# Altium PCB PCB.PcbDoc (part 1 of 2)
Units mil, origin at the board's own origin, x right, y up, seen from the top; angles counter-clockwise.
Board outline 2952.76 x 1850.39 mil, 2 copper layers (Top Layer, Bottom Layer), stack 21 mil thick; 67 components, 133 nets, 435 pads, 333 vias.
Unrouted connection lines stored in the file: 207.
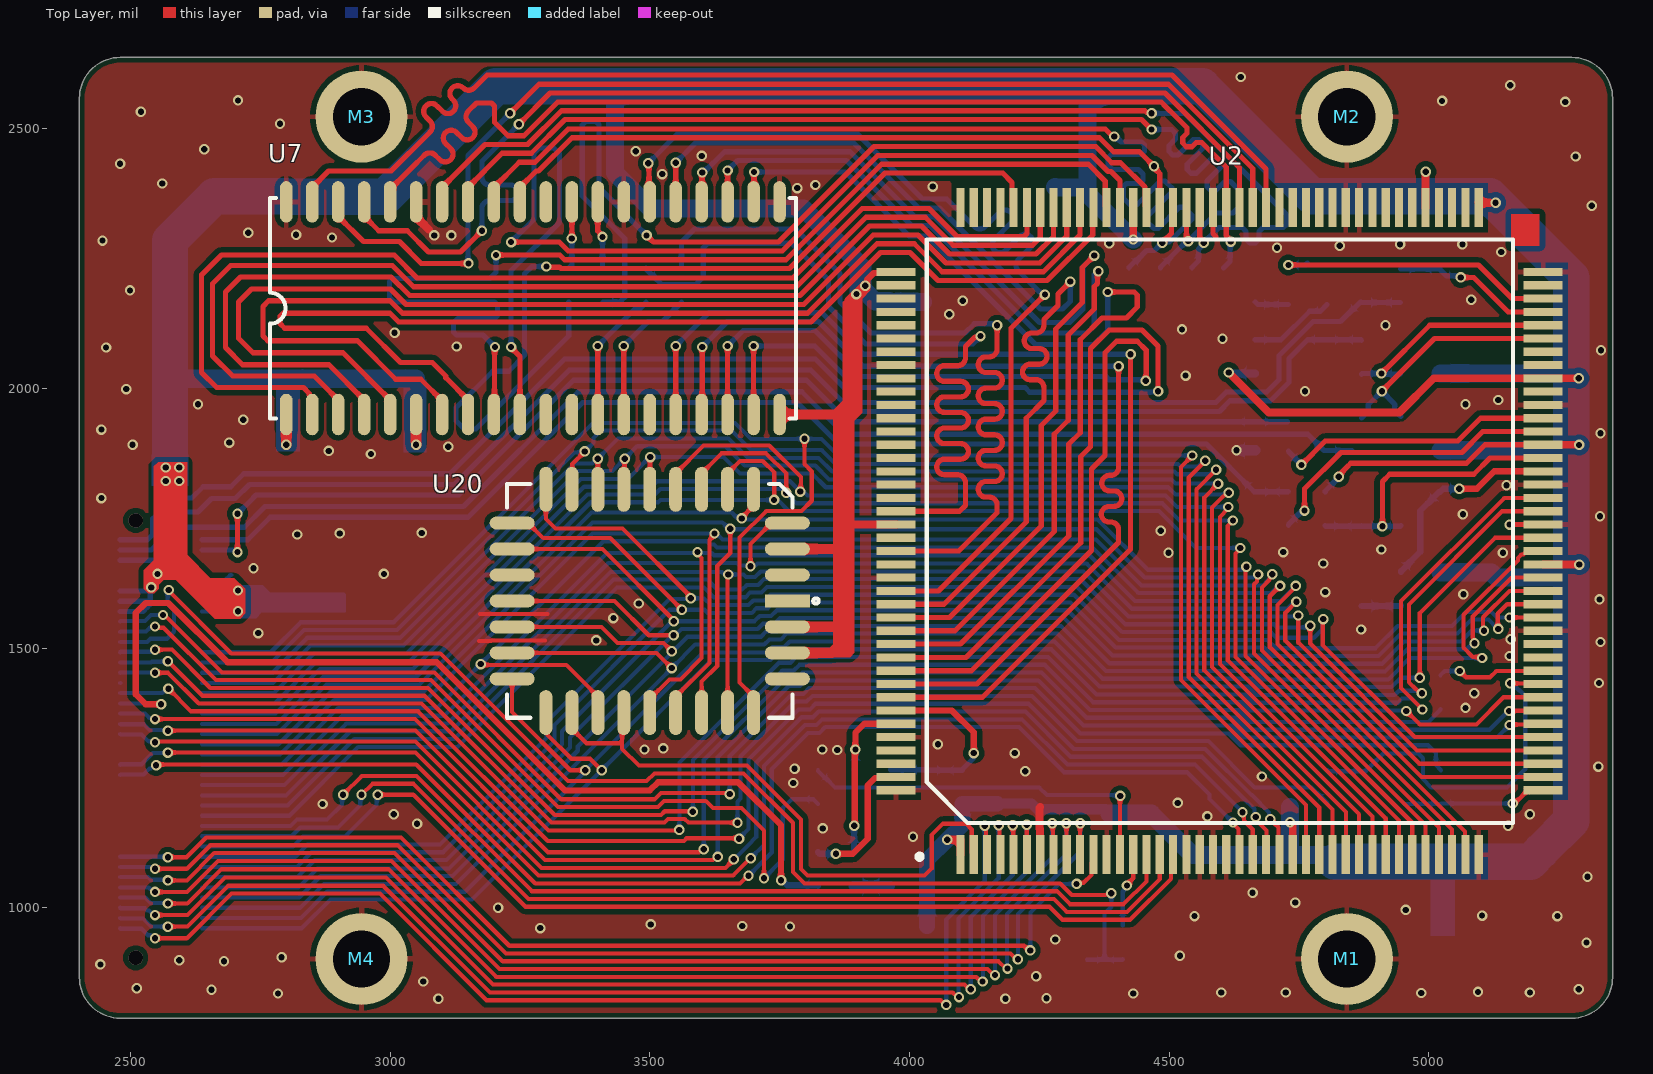
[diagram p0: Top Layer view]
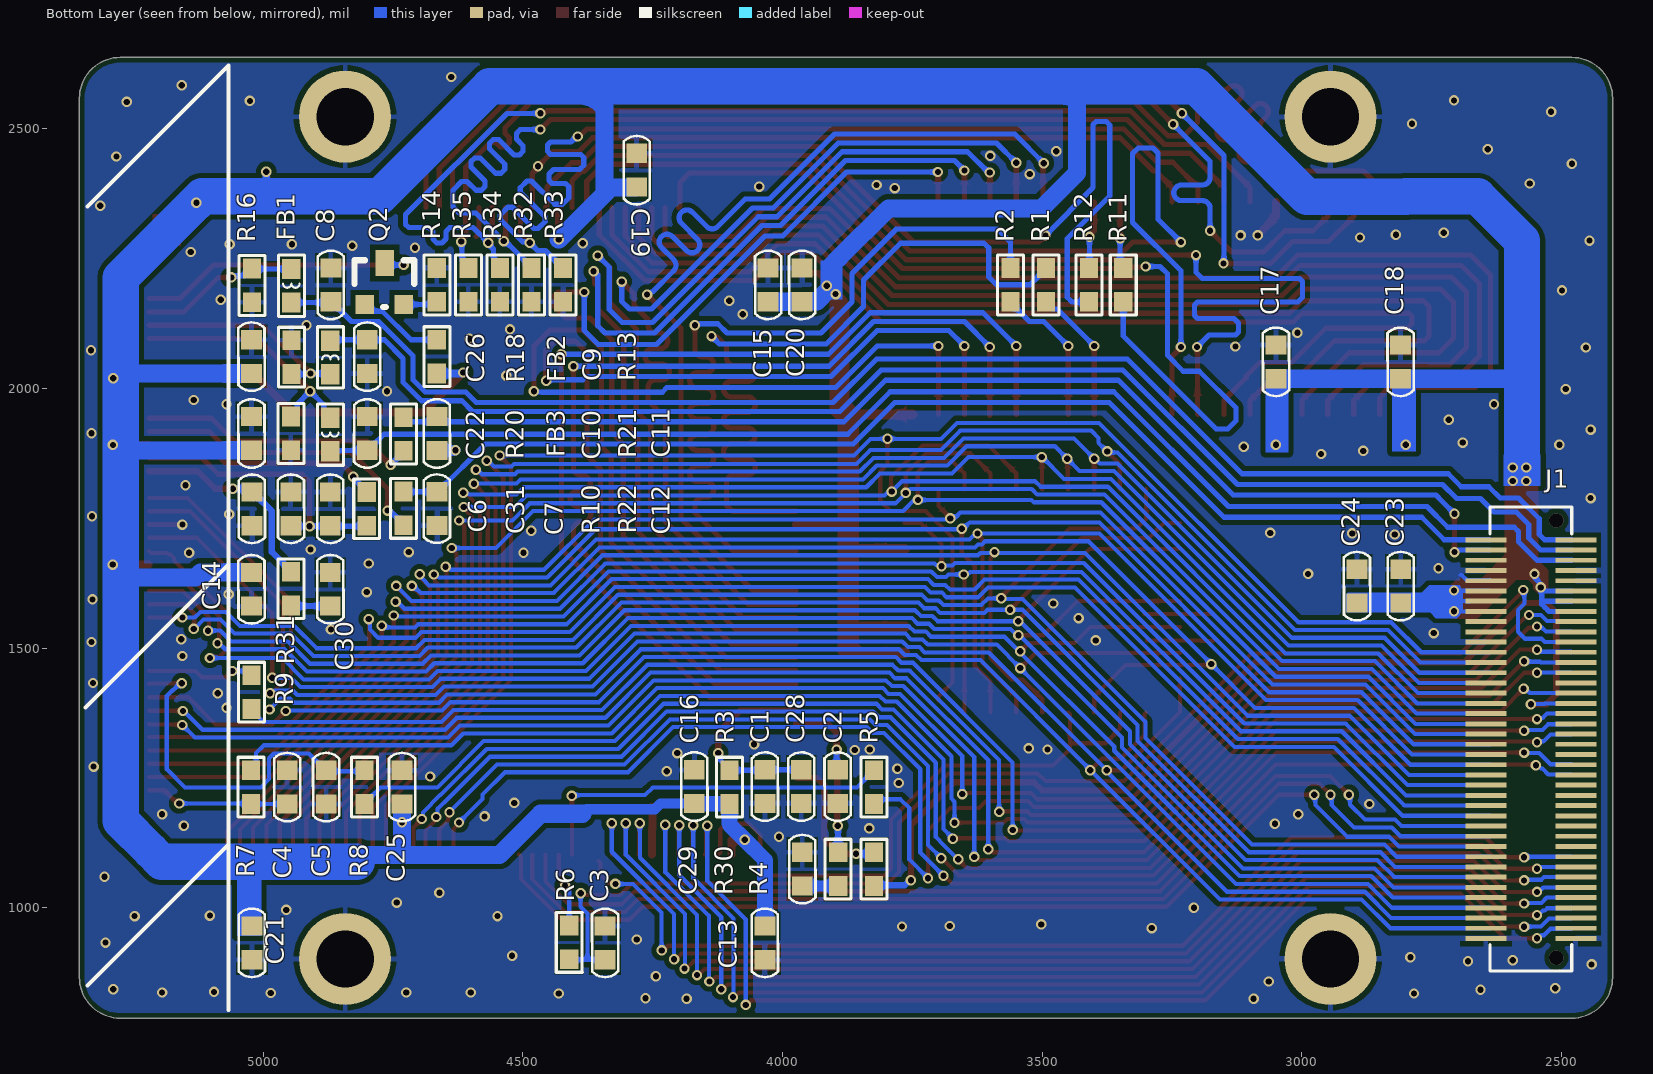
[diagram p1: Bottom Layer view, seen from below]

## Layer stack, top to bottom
Top Solder: solder mask 0.4, Solder Resist, Dk 3.5
Top Layer: signal copper 1.4
Dielectric 1: prepreg 2.8, Composite dielectric, Dk 4.1
Dielectric1: prepreg 12.6, Composite dielectric, Dk 4.1
Dielectric 2: prepreg 2.8, Composite dielectric, Dk 4.1
Bottom Layer: signal copper 1.4
Bottom Solder: solder mask 0.4, Solder Resist, Dk 3.5

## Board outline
2401.57,866.14 ccw(c2480.31,866.14) 2480.31,787.4 5275.59,787.4 ccw(c5275.59,866.14) 5354.33,866.14 5354.33,2559.06 ccw(c5275.59,2559.06) 5275.59,2637.8 2480.31,2637.8 ccw(c2480.31,2559.06) 2401.57,2559.06

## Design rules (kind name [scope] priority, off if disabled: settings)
BoardOutlineClearance [All] p1: gap=0 ignorepadtopadclearanceinfootprint=FALSE except(10: Poly-OutlineEdge Poly-CavityEdge Poly-CutoutEdge Poly-SplitBarrior)
Clearance [All] p1: gap=7 ignorepadtopadclearanceinfootprint=FALSE except(0: Arc-Hole Track-Hole SMDPad-Hole THPad-Hole Via-Hole Fill-Hole Poly-Hole Region-Hole Text-Hole; 10: Arc-Fill Arc-Poly Arc-Region Track-Fill Track-Poly Track-Region SMDPad-Fill SMDPad-Poly SMDPad-Region THPad-Fill THPad-Poly THPad-Region Via-Fill Via-Poly Via-Region Fill-Fill Fill-Poly Fill-Region Poly-Poly Poly-Region Region-Region)
ComponentClearance [All] p1: gap=0 collisioncheckmode=3 verticalgap=0 showdistances=FALSE
HoleSize [All] p1: absolutevalues=TRUE maxlimit=1000 minlimit=1 maxpercent=80.000 minpercent=20.000
HoleToHoleClearance [All] p1: gap=0 allowstackedmicrovias=TRUE
MinimumSolderMaskSliver [All] p1: minsoldermaskwidth=0
PlaneClearance [All] p1: clearance=0
PolygonConnect PolygonConnect_1 [InNet('GND')] p1: thpad.connectstyle=Relief thpad.reliefconductorwidth=10 thpad.reliefentries=4 thpad.polygonreliefangle="90 Angle" thpad.airgapwidth=10 smdpad.connectstyle=Relief smdpad.reliefconductorwidth=10 smdpad.reliefentries=4 smdpad.polygonreliefangle="90 Angle" smdpad.airgapwidth=10 via.connectstyle=Direct via.reliefconductorwidth=10 via.reliefentries=4 via.polygonreliefangle="90 Angle" via.airgapwidth=10
PolygonConnect [All] p2: connectstyle=Direct reliefconductorwidth=10 reliefentries=4 polygonreliefangle="90 Angle" airgapwidth=10
RoutingVias [All] p1: holewidth=14 width=27 viastyle="Through Hole" minholewidth=10 minwidth=18 maxholewidth=50 maxwidth=100
SilkToSilkClearance [All] p1: silktosilkclearance=0
SilkToSolderMaskClearance [IsPad] p1: minsilkscreentomaskgap=0 clearancetoexposedcopper=TRUE
SolderMaskExpansion [All] p1: expansion=4 istentingtop=FALSE
Width [All] p1: maxlimit=200 minlimit=8 preferedwidth=8 minimp=50.000000 maximp=50.000000 favimp=50.000000
23 further rules are at their usual default settings.

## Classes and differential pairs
net class RAM-D: MD16 MD17 MD18 MD19 MD20 MD21 MD22 MD23 MD24 MD25 MD26 MD27 MD28 MD29 MD30 MD31
net class RAM-A: CAS# NetR1_2 NetR2_2 NetR11_1 NetR12_1 RAS# VA0 VA1 VA2 VA3 VA4 VA5 VA6 VA7 VA8 WE2# WE3#

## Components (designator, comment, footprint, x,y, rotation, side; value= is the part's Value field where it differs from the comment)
C1 "0.1uf" C0603 4034,1266 r270 bottom
C2 "0.1uf" C0603 3894,1266 r270 bottom
C3 "47pf" C0603 4342,900 r90 bottom
C4 "470pf" C0603 4954,1200 r90 bottom
C5 "47pf" C0603 4879,1264.96 r270 bottom
C6 "0.1uf" C0603 5022,1800.96 r270 bottom
C7 "0.1uf" C0603 4871,1736 r90 bottom
C8 "47pf" C0603 4870,2167 r90 bottom
C9 "47pf" C0603 4800,2093.98 r270 bottom
C10 "47pf" C0603 4800,1881 r90 bottom
C11 "47pf" C0603 4665.75,1945.96 r270 bottom
C12 "47pf" C0603 4665.75,1801.23 r270 bottom
C13 "10uf" C0603 4034,964.96 r270 bottom
C14 "0.1uf" C0603 5022.75,1646 r270 bottom
C15 "0.1uf" C0603 4028,2167.04 r90 bottom
C16 "0.1uf" C0603 4170,1201.04 r90 bottom
C17 "0.1uf" C0603 3050,2019.02 r90 bottom
C18 "0.1uf" C0603 2810,2019.02 r90 bottom
C19 "0.1uf" C0603 4281,2388 r90 bottom
C20 "10uf" C0603 3962.65,2167.04 r90 bottom
C21 "10uf" C0603 5022,964.96 r270 bottom
C22 "0.1uf" C0603 5023,1881 r90 bottom
C23 "10uf" C0603 2809.75,1587.04 r90 bottom
C24 "10uf" C0603 2894,1587.04 r90 bottom
C25 "0.1uf" C0603 4733,1200 r90 bottom
C26 "0.1uf" C0603 5023,2029 r90 bottom
C28 "10uf" C0603 3964,1266 r270 bottom
C29 "1uf" C0603 3962,1042 r90 bottom
C30 "1uf" C0603 4871,1581.04 r90 bottom
C31 "0.1uf" C0603 4947,1736 r90 bottom
FB1 "68R 100Mhz" L0603 4946,2198 r90 bottom
FB2 "68R 100Mhz" L0603 4871,2060 r270 bottom
FB3 "68R 100Mhz" L0603 4871,1911.28 r90 bottom
J1 "CON40x2" BTB0.5-80P 2480.31,940.94 r90 bottom locked
M1 "CON1" M2.5 4842.52,901.57 r0 top locked
M2 "CON1" M2.5 4842.52,2523.62 r0 top locked
M3 "CON1" M2.5 2944.88,2523.62 r0 top locked
M4 "CON1" M2.5 2944.88,901.57 r0 top locked
Q2 "3904" SOT23 4767,2202 r180 bottom
R1 "33" R0603 3493,2167 r90 bottom
R2 "33" R0603 3561,2167 r90 bottom
R3 "33" R0603 4102,1200 r90 bottom
R4 "33" R0603 3824,1042 r90 bottom
R5 "33" R0603 3824,1200 r90 bottom
R6 "33" R0603 4411,901 r90 bottom
R7 "1k" R0603 5024,1265 r270 bottom
R8 "33" R0603 4805,1265 r270 bottom
R9 "33" R0603 5023.1,1448 r270 bottom
R10 "33" R0603 4801,1736 r90 bottom
R11 "33" R0603 3344,2167 r90 bottom
R12 "33" R0603 3410,2167 r90 bottom
R13 "1k" R0603 4666,2093.97 r270 bottom
R14 "360" R0603 4666,2232 r270 bottom
R16 "150" R0603 5022,2166 r90 bottom
R18 "150" R0603 4946,2093 r270 bottom
R20 "150" R0603 4947,1881 r90 bottom
R21 "33" R0603 4729.9,1880 r90 bottom
R22 "33" R0603 4729.9,1736.75 r90 bottom
R30 "75" R0603 3893,1107 r270 bottom
R31 "75" R0603 4947,1647 r270 bottom
R32 "4.7k" R0603 4483.75,2167 r90 bottom
R33 "4.7k" R0603 4423,2167 r90 bottom
R34 "4.7k" R0603 4544.5,2167 r90 bottom
R35 "4.7k" R0603 4605.25,2167 r90 bottom
U2 "GD5422" QFP160 4098.43,1102.36 r90 top locked
U7 "16256" SOJ-40 2800,1950 r90 top locked
U20 "29C512_PLCC32" PLCC32S 3765,1591 r270 top

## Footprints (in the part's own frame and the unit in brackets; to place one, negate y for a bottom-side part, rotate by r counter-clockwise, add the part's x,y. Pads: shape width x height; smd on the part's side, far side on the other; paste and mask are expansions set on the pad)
BTB0.5-80P [mm]
  rect 0.24x2 smd: 1(0,-0.2) 2(0,4.2) 3(0.5,-0.2) 4(0.5,4.2) 5(1,-0.2) 6(1,4.2) 7(1.5,-0.2) 8(1.5,4.2) 9(2,-0.2) 10(2,4.2) 11(2.5,-0.2) 12(2.5,4.2) 13(3,-0.2) 14(3,4.2) 15(3.5,-0.2) 16(3.5,4.2) 17(4,-0.2) 18(4,4.2) 19(4.5,-0.2) 20(4.5,4.2) 21(5,-0.2) 22(5,4.2) 23(5.5,-0.2) 24(5.5,4.2) 25(6,-0.2) 26(6,4.2) 27(6.5,-0.2) 28(6.5,4.2) 29(7,-0.2) 30(7,4.2) 31(7.5,-0.2) 32(7.5,4.2) 33(8,-0.2) 34(8,4.2) 35(8.5,-0.2) 36(8.5,4.2) 37(9,-0.2) 38(9,4.2) 39(9.5,-0.2) 40(9.5,4.2) 41(10,-0.2) 42(10,4.2) 43(10.5,-0.2) 44(10.5,4.2) 45(11,-0.2) 46(11,4.2) 47(11.5,-0.2) 48(11.5,4.2) 49(12,-0.2) 50(12,4.2) 51(12.5,-0.2) 52(12.5,4.2) 53(13,-0.2) 54(13,4.2) 55(13.5,-0.2) 56(13.5,4.2) 57(14,-0.2) 58(14,4.2) 59(14.5,-0.2) 60(14.5,4.2) 61(15,-0.2) 62(15,4.2) 63(15.5,-0.2) 64(15.5,4.2) 65(16,-0.2) 66(16,4.2) 67(16.5,-0.2) 68(16.5,4.2) 69(17,-0.2) 70(17,4.2) 71(17.5,-0.2) 72(17.5,4.2) 73(18,-0.2) 74(18,4.2) 75(18.5,-0.2) 76(18.5,4.2) 77(19,-0.2) 78(19,4.2) 79(19.5,-0.2) 80(19.5,4.2)
  silkscreen extent -1.6,0 21.1,4
C0603 [mil]
  rect 37.01x40 smd: 1(0,0)
  rect 37x40 smd: 2(64.98,0)
  silkscreen extent -34,-25 98,25
L0603 [mm]
  rect 1x0.9 smd: 1(-0.82,0) 2(0.82,0)
  silkscreen extent -1.5,-0.64 1.5,0.64
M2.5 [mm]
  round 4.5 hole 2.8: 1(0,0)
PLCC32S [mil]
  rect 25x86.61 smd: 1(0,0)
  oval 25x86.61 smd: 2(-50,0) 3(-100,0) 4(-150,0) 14(-150,-530) 15(-100,-530) 16(-50,-530) 17(0,-530) 18(50,-530) 19(100,-530) 20(150,-530) 30(150,0) 31(100,0) 32(50,0)
  oval 86.61x25 smd: 5(-215,-65) 6(-215,-115) 7(-215,-165) 8(-215,-215) 9(-215,-265) 10(-215,-315) 11(-215,-365) 12(-215,-415) 13(-215,-465) 21(215,-465) 22(215,-415) 23(215,-365) 24(215,-315) 25(215,-265) 26(215,-215) 27(215,-165) 28(215,-115) 29(215,-65)
  silkscreen extent -225,-540 225,60
QFP160 [mm] "160-Pin Plastic Quad Flat Pack (PQFP)"
  rect 1.9x0.4 smd: 1(0,0) 2(0,-0.65) 3(0,-1.3) 4(0,-1.95) 5(0,-2.6) 6(0,-3.25) 7(0,-3.9) 8(0,-4.55) 9(0,-5.2) 10(0,-5.85) 11(0,-6.5) 12(0,-7.15) 13(0,-7.8) 14(0,-8.45) 15(0,-9.1) 16(0,-9.75) 17(0,-10.4) 18(0,-11.05) 19(0,-11.7) 20(0,-12.35) 21(0,-13) 22(0,-13.65) 23(0,-14.3) 24(0,-14.95) 25(0,-15.6) 26(0,-16.25) 27(0,-16.9) 28(0,-17.55) 29(0,-18.2) 30(0,-18.85) 31(0,-19.5) 32(0,-20.15) 33(0,-20.8) 34(0,-21.45) 35(0,-22.1) 36(0,-22.75) 37(0,-23.4) 38(0,-24.05) 39(0,-24.7) 40(0,-25.35) 81(31.65,-25.35) 82(31.65,-24.7) 83(31.65,-24.05) 84(31.65,-23.4) 85(31.65,-22.75) 86(31.65,-22.1) 87(31.65,-21.45) 88(31.65,-20.8) 89(31.65,-20.15) 90(31.65,-19.5) 91(31.65,-18.85) 92(31.65,-18.2) 93(31.65,-17.55) 94(31.65,-16.9) 95(31.65,-16.25) 96(31.65,-15.6) 97(31.65,-14.95) 98(31.65,-14.3) 99(31.65,-13.65) 100(31.65,-13) 101(31.65,-12.35) 102(31.65,-11.7) 103(31.65,-11.05) 104(31.65,-10.4) 105(31.65,-9.75) 106(31.65,-9.1) 107(31.65,-8.45) 108(31.65,-7.8) 109(31.65,-7.15) 110(31.65,-6.5) 111(31.65,-5.85) 112(31.65,-5.2) 113(31.65,-4.55) 114(31.65,-3.9) 115(31.65,-3.25) 116(31.65,-2.6) 117(31.65,-1.95) 118(31.65,-1.3) 119(31.65,-0.65) 120(31.65,0)
  rect 0.4x1.9 smd: 41(3.15,-28.5) 42(3.8,-28.5) 43(4.45,-28.5) 44(5.1,-28.5) 45(5.75,-28.5) 46(6.4,-28.5) 47(7.05,-28.5) 48(7.7,-28.5) 49(8.35,-28.5) 50(9,-28.5) 51(9.65,-28.5) 52(10.3,-28.5) 53(10.95,-28.5) 54(11.6,-28.5) 55(12.25,-28.5) 56(12.9,-28.5) 57(13.55,-28.5) 58(14.2,-28.5) 59(14.85,-28.5) 60(15.5,-28.5) 61(16.15,-28.5) 62(16.8,-28.5) 63(17.45,-28.5) 64(18.1,-28.5) 65(18.75,-28.5) 66(19.4,-28.5) 67(20.05,-28.5) 68(20.7,-28.5) 69(21.35,-28.5) 70(22,-28.5) 71(22.65,-28.5) 72(23.3,-28.5) 73(23.95,-28.5) 74(24.6,-28.5) 75(25.25,-28.5) 76(25.9,-28.5) 77(26.55,-28.5) 78(27.2,-28.5) 79(27.85,-28.5) 80(28.5,-28.5) 121(28.5,3.15) 122(27.85,3.15) 123(27.2,3.15) 124(26.55,3.15) 125(25.9,3.15) 126(25.25,3.15) 127(24.6,3.15) 128(23.95,3.15) 129(23.3,3.15) 130(22.65,3.15) 131(22,3.15) 132(21.35,3.15) 133(20.7,3.15) 134(20.05,3.15) 135(19.4,3.15) 136(18.75,3.15) 137(18.1,3.15) 138(17.45,3.15) 139(16.8,3.15) 140(16.15,3.15) 141(15.5,3.15) 142(14.85,3.15) 143(14.2,3.15) 144(13.55,3.15) 145(12.9,3.15) 146(12.25,3.15) 147(11.6,3.15) 148(10.95,3.15) 149(10.3,3.15) 150(9.65,3.15) 151(9,3.15) 152(8.35,3.15) 153(7.7,3.15) 154(7.05,3.15) 155(6.4,3.15) 156(5.75,3.15) 157(5.1,3.15) 158(4.45,3.15) 159(3.8,3.15) 160(3.15,3.15)
  silkscreen extent -0.22,-27.03 30.1,2.12
R0603 [mil]
  rect 38x35 smd: 1(0,0) 2(65,0)
  silkscreen extent -25,-25 90,25
SOJ-40 [mil] "薄贴片"
  oval 80x24 smd: 1(0,0) 2(0,-50) 3(0,-100) 4(0,-150) 5(0,-200) 6(0,-250) 7(0,-300) 8(0,-350) 9(0,-400) 10(0,-450) 11(0,-500) 12(0,-550) 13(0,-600) 14(0,-650) 15(0,-700) 16(0,-750) 17(0,-800) 18(0,-850) 19(0,-900) 20(0,-950) 21(409.45,-950) 22(409.45,-900) 23(409.45,-850) 24(409.45,-800) 25(409.45,-750) 26(409.45,-700) 27(409.45,-650) 28(409.45,-600) 29(409.45,-550) 30(409.45,-500) 31(409.45,-450) 32(409.45,-400) 33(409.45,-350) 34(409.45,-300) 35(409.45,-250) 36(409.45,-200) 37(409.45,-150) 38(409.45,-100) 39(409.45,-50) 40(409.45,0)
  silkscreen extent -8,-981 417,31
SOT23 [mil]
  rect 36x36 smd: B(-37.5,-40) E(37.5,-40)
  rect 36x50 smd: C(0.5,40)
  silkscreen extent -58,-45 58,45

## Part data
C1 C2 C13 C14 C15 C16 C17 C18 C19 C20 C21 C22 C23 C24 C25 C26 C28 C29 C30: library part 0CAP
C3 C4 C5 C6 C7 C8 C9 C10 C11 C12 C31: library part CAP
FB1 FB2 FB3: library part L
Q2: library part 0NPN
R1 R2 R3 R4 R5 R6 R7 R8 R9 R10 R11 R12 R13 R14 R16 R18 R20 R21 R22 R30 R31 R32 R33 R34 R35: library part RES2

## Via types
v1: diameter 20, hole 12, Top Layer to Bottom Layer, tented both sides, 331 vias
v2: diameter 27.56, hole 27.56, Top Layer to Bottom Layer, 2 vias

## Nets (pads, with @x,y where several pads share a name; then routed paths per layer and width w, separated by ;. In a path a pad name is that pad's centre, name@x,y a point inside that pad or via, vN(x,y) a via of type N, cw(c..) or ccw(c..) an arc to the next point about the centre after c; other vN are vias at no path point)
A0: J1.58 U2.27 U20.29 | length 3612.3
  Top Layer w8: U20.29@3700,1399 3700,1406.81 3673,1433.81 3673,1713.04 3724.46,1764.5 3792.5,1764.5 3812,1784 3812,1840.38 3798,1854.38 v1(3798,1903.19) ; v1(4544.92,1871) 4544.92,1870.92 4523,1849 4523,1438.59 4763.78,1197.81 U2.27@4763.78,1102.36
  Bottom Layer w8: J1.58@2637.8,1492.13 2770.13,1492.13 2828,1550 3006.87,1550 3390.87,1934 3664,1934 3694.81,1903.19 v1(3798,1903.19) 3830.66,1903.19 3862.85,1871 v1(4544.92,1871)
A1: J1.56 U2.28 U20.12 | length 3115.1
  Top Layer w8: U20.12@3350,1806 3350.73,1806.73 3350.73,1854.73 v1(3375,1879) ; v1(4570,1861) 4538,1829 4538,1444.8 4789.37,1193.43 U2.28@4789.37,1102.36
  Bottom Layer w8: J1.56@2637.8,1472.44 2771.65,1472.44 2834.21,1535 3013.08,1535 3354.79,1876.7 3372.7,1876.7 3391.5,1895.5 3391.5,1904.8 3405.7,1919 3657.79,1919 3695.29,1881.5 3831.14,1881.5 3857.64,1855 4517,1855 4522,1850 4555.75,1850 4566.75,1861 v1(4570,1861)
A2: J1.54 U2.29 U20.11 | length 3096.3
  Top Layer w8: U20.11@3400,1806 v1(3400,1865) ; v1(4590.65,1843.61) 4553,1805.96 4553,1451.02 4814.96,1189.06 U2.29@4814.96,1102.36
  Bottom Layer w8: J1.54@2637.8,1452.76 2773.18,1452.76 2840.43,1520 3019.29,1520 3355.29,1856 3389.31,1856 3398.31,1865 v1(3400,1865) 3439,1904 3651.57,1904 3689.07,1866.5 3824.93,1866.5 3851.43,1840 4510.79,1840 4515.79,1835 4578.8,1835 4587.41,1843.61 v1(4590.65,1843.61)
A3: J1.52 U2.30 U20.10 | length 3072
  Top Layer w8: U20.10@3450,1806 3451,1807 3451,1864 v1(3452,1865) ; v1(4594.61,1816.9) 4568,1790.29 4568,1457.23 4840.55,1184.68 U2.30@4840.55,1102.36
  Bottom Layer w8: J1.52@2637.8,1433.07 2774.71,1433.07 2846.64,1505 3025.51,1505 3361.51,1841 3428,1841 v1(3452,1865) ; v1@3454,1866 3454,1867 3476,1889 3645.36,1889 3682.86,1851.5 3818.71,1851.5 3845.21,1825 4504.57,1825 4512.67,1816.9 v1(4594.61,1816.9)
A4: J1.50 U2.31 U20.9 | length 3088.9
  Top Layer w8: U20.9@3500,1806 3500.5,1806.5 3500.5,1867.5 v1(3501,1868) ; v1(4615.11,1799.33) 4611.86,1799.33 4605.53,1793 4605.3,1793 4583,1770.7 4583,1463.44 4866.14,1180.3 U2.31@4866.14,1102.36
  Bottom Layer w8: J1.50@2637.8,1413.39 2776.24,1413.39 2852.85,1490 3031.72,1490 3367.72,1826 3458,1826 3500,1868 v1(3501,1868) 3642,1868 3673.5,1836.5 3812.5,1836.5 3839,1810 4498.36,1810 4512.46,1795.9 4603.31,1795.9 4604.44,1797.04 4612.82,1797.04 v1(4615.11,1799.33)
A5: J1.48 U2.32 U20.8 | length 3325.4
  Top Layer w8: U20.8@3550,1806 3550,1836.81 3603.5,1890.31 3730.12,1890.31 3791,1829.43 3791,1802.72 v1(3789.78,1801.5) ; v1(4614,1772) 4614,1768.89 4598,1752.89 4598,1469.65 4891.73,1175.92 U2.32@4891.73,1102.36
  Bottom Layer w8: J1.48@2637.8,1393.7 2777.77,1393.7 2859.07,1475 3037.93,1475 3373.93,1811 3503.51,1811 3514.01,1821.5 3770.09,1821.5 3786.01,1805.58 3789.58,1805.58 3791,1807 3804,1794 4493.15,1794 4515.15,1772 v1(4614,1772) ; v1(3789.78,1801.5) v1@3793.14,1804.86
A6: J1.46 U2.33 U20.7 | length 3226.4
  Top Layer w8: U20.7@3600,1806 3600,1836.81 3638.5,1875.31 3723.91,1875.31 3763,1836.21 3763,1799.11 v1(3762.89,1799) ; v1(4623,1746) 4623,1745.31 4613,1735.31 4613,1476.87 4917.32,1172.55 U2.33@4917.32,1102.36
  Bottom Layer w8: J1.46@2637.8,1374.02 2779.3,1374.02 2865.28,1460 3044.15,1460 3380.15,1796 3509.73,1796 3520.23,1806.5 3754.25,1806.5 3761.75,1799 3762.58,1799 3782.58,1779 4486.93,1779 4519.93,1746 v1(4623,1746)
A7: J1.44 U2.34 U20.6 | length 3130.9
  Top Layer w8: U20.6@3650,1806 3650,1836.81 3673.5,1860.31 3717.69,1860.31 3739.92,1838.08 3739.92,1785.91 v1(3739.51,1785.5) ; v1(4637,1693) 4637,1691.31 4628,1682.31 4628,1483.08 4942.91,1168.17 U2.34@4942.91,1102.36
  Bottom Layer w8: J1.44@2637.8,1354.33 2780.82,1354.33 2871.49,1445 3050.36,1445 3386.36,1781 3515.94,1781 3520.44,1785.5 v1@3739.92,1785.5 ; v1@3743,1787 3744.69,1787 3767.69,1764 4480.72,1764 4551.72,1693 v1(4637,1693)
A8: J1.42 U2.35 U20.5 | length 2990
  Top Layer w8: v1(3677,1750) 3677,1751.1 3700,1774.1 U20.5@3700,1806 ; v1(4649,1657) 4647,1655 4647,1485.29 4968.5,1163.79 U2.35@4968.5,1102.36
  Bottom Layer w8: J1.42@2637.8,1334.65 2782.35,1334.65 2877.71,1430 3056.57,1430 3387.57,1761 3658,1761 3669,1750 v1(3677,1750) 3679,1748 4362.54,1748 4459.54,1651 4639.75,1651 4645.75,1657 v1(4649,1657)
A9: J1.40 U2.36 U20.27 | length 3313.4
  Top Layer w8: U20.27@3600,1376 3600,1435.59 3630,1465.59 3630,1658.56 3655,1683.56 v1(3655,1730) ; v1(4671.64,1642) 4669.34,1639.7 4669.34,1628.56 4664,1623.21 4664,1489.51 4994.09,1159.41 U2.36@4994.09,1102.36
  Bottom Layer w8: J1.40@2637.8,1314.96 2784.71,1314.96 2884.75,1415 3062.79,1415 3389.79,1742 3639.75,1742 3651.75,1730 v1(3655,1730) 3656,1729 4360.33,1729 4453.33,1636 4662.39,1636 4668.39,1642 v1(4671.64,1642)
A10: J1.38 U2.37 U20.26 | length 3353.2
  Top Layer w8: U20.26@3550,1376 3550,1406.81 3615,1471.81 3615,1708.12 3624.61,1717.73 v1(3624.61,1720.98) ; v1(4698.64,1642.2) 4698.64,1638.96 4693.86,1634.18 4693.86,1631.86 4679,1617 4679,1495.72 5019.69,1155.04 U2.37@5019.69,1102.36
  Bottom Layer w8: J1.38@2637.8,1295.28 2787.65,1295.28 2892.37,1400 3069,1400 3390,1721 v1(3624.61,1720.98) ; v1@3625.39,1719.46 3629.37,1719.46 3639.83,1709 4359.12,1709 4447.12,1621 4681.27,1621 4686.92,1626.66 4686.92,1627.24 4698.64,1638.96 v1(4698.64,1642.2)
A11: J1.36 U2.38 U20.23 | length 3255.3
  Top Layer w8: v1(3174.58,1469.42) 3176.5,1467.5 3339.31,1467.5 3400,1406.81 U20.23@3400,1376 ; v1(4714,1620) 4694,1600 4694,1501.93 5045.28,1150.66 U2.38@5045.28,1102.36
  Bottom Layer w8: J1.36@2637.8,1275.59 2790.59,1275.59 2900,1385 3090.15,1385 v1(3174.58,1469.42) 3411.15,1706 3609.89,1706 3615.91,1699.98 3623.66,1699.98 3629.63,1694 4352.9,1694 4440.9,1606 4696.89,1606 4710.89,1620 v1(4714,1620)
A12: J1.34 U2.39 U20.25 | length 3382.2
  Top Layer w8: U20.25@3500,1376 3500,1402.21 3537.79,1440 3559,1440 3600,1481 3600,1673.75 3592,1681.75 v1(3592,1685) ; v1(4744,1620) 4744,1618 4709,1583 4709,1508.15 5070.07,1147.08 5070.07,1103.16 U2.39@5070.87,1102.36
  Bottom Layer w8: J1.34@2637.8,1255.91 2793.91,1255.91 2908,1370 3104.85,1370 3417.85,1683 3590,1683 v1(3592,1685) ; v1@3592,1683 3619.42,1683 3623.42,1679 4346.69,1679 4434.69,1591 4715,1591 v1(4744,1620)
A13: J1.32 U2.42 U20.4 | length 3149.8
  Top Layer w8: v1(3694,1658) 3694,1700.81 3734.19,1741 U20.4@3765,1741 ; v1(4745.35,1589.65) 4724,1568.3 4724,1514.36 4852.18,1386.18 ; 4852.88,1385.48 4975.8,1262.56 4986.39,1251.97 U2.42@5220.47,1251.97
  Bottom Layer w8: J1.32@2637.8,1236.22 2796.85,1236.22 2915.63,1355 3111.07,1355 3420.07,1664 3668,1664 3672.7,1659.3 3692.7,1659.3 v1(3694,1658) 3696.3,1660.3 3704.78,1660.3 3707.49,1663 4341.48,1663 4428.48,1576 4728.45,1576 4742.1,1589.65 v1(4745.35,1589.65)
A14: J1.30 U2.43 U20.28 | length 3221.8
  Top Layer w8: U20.28@3650,1376 3650,1641 v1(3651,1642) ; v1(4749.01,1562.9) 4749.01,1510.56 4827.54,1432.04 4895.29,1364.29 4982.01,1277.56 U2.43@5220.47,1277.56
  Bottom Layer w8: J1.30@2637.8,1216.54 2799.79,1216.54 2923.25,1340 3117.28,1340 3424.28,1647 3639,1647 3641.7,1644.3 3648.7,1644.3 v1(3651,1642) 3680.3,1642 3685.3,1637 3702.7,1637 3713.7,1648 4335.26,1648 4422.26,1561 4747.11,1561 v1(4749.01,1562.9)
A15: J1.28 U2.44 | length 2937
  Top Layer w8: v1(4772,1543) 4772,1508.79 4977.64,1303.15 U2.44@5220.47,1303.15
  Bottom Layer w8: J1.28@2637.8,1196.85 2802.73,1196.85 2930.88,1325 3123.49,1325 3430.49,1632 3611,1632 3630,1613 3677.95,1613 3686.95,1622 3708.91,1622 3719.91,1633 4329.05,1633 4416.05,1546 4702.05,1546 4708.05,1540 v1@4772,1540
A16: J1.26 U2.45 | length 2971.7
  Top Layer w8: v1(4797,1556) 4796,1555 4796,1506 4973.26,1328.74 U2.45@5220.47,1328.74
  Bottom Layer w8: J1.26@2637.8,1177.17 2805.68,1177.17 2938.51,1310 3129.71,1310 3436.71,1617 3604.79,1617 3623.79,1598 3684.16,1598 3693.16,1607 3715.12,1607 3726.12,1618 4322.84,1618 4409.84,1531 4695.84,1531 4706.84,1520 4778.7,1520 4794.7,1536.01 4794.7,1553.7 v1(4797,1556)
A17: J1.24 U2.15 | length 2040.7
  Top Layer w8: v1(2909.45,1217.85) 2945.45,1253.85 3051.01,1253.85 3272.86,1032 4284.43,1032 4309.43,1007 4412.7,1007 4456.69,1050.99 U2.15@4456.69,1102.36
  Bottom Layer w8: J1.24@2637.8,1157.48 2808.27,1157.48 2820.79,1170 2878.66,1170 2907.15,1198.49 2907.15,1215.55 v1(2909.45,1217.85)
A18: J1.22 U2.16 | length 2072.3
  Top Layer w8: v1(2944.88,1217.85) 2965.88,1238.85 3044.8,1238.85 3266.65,1017 4278.21,1017 4303.21,992 4418.91,992 4482.28,1055.37 U2.16@4482.28,1102.36
  Bottom Layer w8: J1.22@2637.8,1137.8 2809.8,1137.8 2827,1155 2899.88,1155 2942.59,1197.7 2942.59,1215.55 v1(2944.88,1217.85)
A19: J1.20 U2.17 | length 2098.5
  Top Layer w8: v1(2976.38,1217.85) 3044.58,1217.85 3260.43,1002 4269.65,1002 4294.65,977 4425.12,977 4504,1055.88 4504,1098.49 U2.17@4507.87,1102.36
  Bottom Layer w8: J1.20@2637.8,1118.11 2813.09,1118.11 2831.98,1137 2913.38,1137 2974.08,1197.7 2974.08,1215.55 v1(2976.38,1217.85)
AEN: J1.43 U2.46 | length 3161.2
  Top Layer w8: v1(2572,1341.18) 3048.89,1341.18 3298.07,1092 3621.75,1092 3627.75,1098 v1(3631,1098) ; v1(5156.08,1352.02) 5157.23,1353.18 5219.32,1353.18 U2.46@5220.47,1354.33
  Bottom Layer w8: J1.43@2480.31,1354.33 2481.24,1353.41 2525.98,1353.41 2536.92,1342.46 2570.72,1342.46 v1(2572,1341.18) ; v1(3631,1098) 3631,1290.28 3767.72,1427 3789.68,1427 3800.68,1438 4248.28,1438 4335.28,1351 4621.28,1351 4644.28,1328 5132.06,1328 v1(5156.08,1352.02)
ALE: J1.49 U2.25 | length 2702.7
  Top Layer w8: v1(2573,1422) 2616.54,1378.46 3054.03,1378.46 3303.49,1129 3565.7,1129 3570.7,1134 3671,1134 v1(3672,1133) ; v1(4695,1170.98) 4710.97,1155.01 4710.97,1103.99 U2.25@4712.6,1102.36
  Bottom Layer w8: J1.49@2480.31,1413.39 2561.14,1413.39 2569.75,1422 v1(2573,1422) ; v1(3672,1133) 3672,1133.77 3690,1151.77 3690,1285.64 3786.36,1382 3808.32,1382 3819.32,1393 4229.64,1393 4316.64,1306 4569.79,1306 4658.79,1217 4659.57,1217 4692.7,1183.87 4692.7,1173.27 v1(4695,1170.98)
BHE#: J1.41 U2.24 | length 2676.7
  Top Layer w8: v1(2547.24,1318.9) 2548.35,1320 3048.85,1320 3291.85,1077 3646,1077 3661.65,1092.65 v1(3661.65,1093.35) ; v1(4667,1175) 4669.3,1172.7 4669.3,1166.98 4687.49,1148.79 4687.49,1102.85 U2.24@4687.01,1102.36
  Bottom Layer w8: J1.41@2480.31,1334.65 2481.24,1333.72 2521.4,1333.72 2533.93,1321.19 2544.95,1321.19 v1(2547.24,1318.9) ; v1(3661.65,1093.35) 3662.35,1093.35 3689,1120 3689,1120.3 3705,1136.3 3705,1279.43 3792.57,1367 3814.54,1367 3825.54,1378 4223.43,1378 4310.43,1291 4563.57,1291 4652.57,1202 4653.36,1202 4664.7,1190.66 4664.7,1177.3 v1(4667,1175)
CAS#: R1.1 U7.13 | length 261.1
  Top Layer w10: U7.13@3400,1950 v1(3400,2082)
  Bottom Layer w10: v1(3400,2082) 3471,2153 3480.5,2153 3493,2165.5 R1.1@3493,2167
CLKIN: R4.2 U2.159 | length 273.1
  Top Layer w12: v1(3858.5,1104) 3891,1104 3920,1133 3920,1235.63 3934.47,1250.09 3972.54,1250.09 U2.159@3974.41,1251.97
  Bottom Layer w12: R4.2@3824,1107 3827,1104 v1(3858.5,1104)
D0: J1.18 U2.54 U20.13 | length 3293.9
  Top Layer w8: U20.13@3300,1806 3300,1749 3318.28,1730.73 3447.27,1730.73 3579,1599 v1(3579,1596) ; v1(5156,1559) U2.54@5220.44,1559.03
  Bottom Layer w8: J1.18@2637.8,1098.43 2817.44,1098.43 2841.02,1122 3096,1122 3301.29,1327.29 3301.29,1358.2 3538.09,1595 3578,1595 v1(3579,1596) ; v1@3583,1596 3604.57,1596 3617.57,1583 3690.38,1583 3699.38,1592 3721.34,1592 3732.34,1603 4316.62,1603 4403.62,1516 4689.62,1516 4705.62,1500 4897.51,1500 4940.51,1543 5045,1543 5072,1570 5121.21,1570 5132.21,1559 v1(5156,1559)
D1: J1.16 U2.55 U20.14 | length 3329.9
  Top Layer w8: U20.14@3235,1741 3265.81,1741 3294.81,1712 3423.88,1712 v1(3561.88,1574) ; v1(5133.87,1537.1) 5133,1537.98 5133,1566.36 5151.29,1584.65 U2.55@5220.47,1584.65
  Bottom Layer w8: J1.16@2637.8,1078.74 2820.46,1078.74 2848.72,1107 3102.21,1107 3316.29,1321.07 3316.29,1351.99 3538.3,1574 v1(3561.88,1574) 3605.36,1574 3611.36,1568 3696.59,1568 3705.59,1577 3727.55,1577 3738.55,1588 4310.41,1588 4397.41,1501 4683.41,1501 4699.41,1485 4903.72,1485 4946.72,1528 5055.79,1528 5082.79,1555 5115,1555 5132.9,1537.1 v1(5133.87,1537.1)
D2: J1.14 U2.56 U20.15 | length 3295.8
  Top Layer w8: U20.15@3235,1691 3409,1691 3546.25,1553.75 v1(3546.25,1551.98) ; v1(5106.68,1533.62) 5105,1535.3 5105,1559.57 5155.66,1610.24 U2.56@5220.47,1610.24
  Bottom Layer w8: J1.14@2637.8,1059.06 2821.99,1059.06 2854.93,1092 3108.43,1092 3331.29,1314.86 3331.29,1339.99 v1@3543.3,1552 ; v1(3546.25,1551.98) 3701.8,1552 3711.8,1562 3733.76,1562 3744.76,1573 4304.2,1573 4391.2,1486 4677.2,1486 4693.2,1470 4909.93,1470 4952.93,1513 5062,1513 5083,1534 5106.3,1534 v1(5106.68,1533.62)
D3: J1.12 U2.57 U20.17 | length 3299.2
  Top Layer w8: U20.17@3235,1591 3432,1591 3498.02,1524.98 v1(3546,1524.98) ; v1(5088.35,1509.65) 5086.05,1511.95 5086.05,1519.28 5085,1520.34 5085,1560.79 5160.04,1635.83 U2.57@5220.47,1635.83
  Bottom Layer w8: J1.12@2637.8,1039.37 2823.52,1039.37 2860.15,1076 3113.64,1076 3346.29,1308.65 3346.29,1327.68 3543.58,1524.98 v1(3546,1524.98) 3549.27,1525 3561.27,1537 3708.02,1537 3718.02,1547 3739.98,1547 3750.98,1558 4297.98,1558 4384.98,1471 4670.98,1471 4686.98,1455 4916.15,1455 4959.15,1498 5037,1498 5073.45,1498 5085.1,1509.65 v1(5088.35,1509.65)
D4: J1.10 U2.59 U20.18 | length 3387.8
  Top Layer w8: U20.18@3235,1541 3407,1541 3438.02,1509.98 3526.47,1509.98 v1(3542.38,1494.07) ; v1(5103,1481) 5100.7,1483.3 5085.01,1483.3 5067.35,1500.95 5067.35,1564.35 5172.07,1669.07 5172.07,1673.85 5178.51,1680.29 5182.38,1680.29 5185.23,1683.13 5216.6,1683.13 U2.59@5220.47,1687.01
  Bottom Layer w8: J1.10@2637.8,1019.69 2825.05,1019.69 2866.36,1061 3119.85,1061 3361.29,1302.43 3361.29,1310.43 v1@3543.58,1492.73 ; v1(3542.38,1494.07) 3544.93,1494.07 3572.85,1522 3714.23,1522 3724.23,1532 3746.19,1532 3757.19,1543 4291.77,1543 4378.77,1456 4664.77,1456 4680.77,1440 4922.36,1440 4963.36,1481 v1(5103,1481)
D5: J1.8 U2.60 U20.19 | length 3355.5
  Top Layer w8: U20.19@3235,1491 3513,1491 v1(3542.28,1461.72) ; v1(4983,1443) 4983,1568 5127.6,1712.6 U2.60@5220.47,1712.6
  Bottom Layer w8: J1.8@2637.8,1000 2826.57,1000 2872.57,1046 3127,1046 3542.28,1461.28 v1(3542.28,1461.72) ; v1@3542.28,1463 3543.55,1463 3587.55,1507 3720.44,1507 3730.44,1517 3752.4,1517 3763.4,1528 4285.56,1528 4372.56,1441 4658.56,1441 4674.56,1425 4928.57,1425 4946.57,1443 v1(4983,1443)
D6: J1.6 U2.62 U20.20 | length 3386.8
  Top Layer w8: U20.20@3235,1441 3235,1376.96 3346.96,1265 v1(3376,1265) ; v1(4987,1413) 4983.75,1413 4974.75,1422 4974.3,1422 4962,1434.3 4962,1584.43 5141.35,1763.78 U2.62@5220.47,1763.78
  Bottom Layer w8: J1.6@2637.8,980.31 2828.1,980.31 2878.79,1031 3144,1031 3376,1263 v1(3376,1265) ; v1@3377,1265 3377,1266 3603,1492 3726.65,1492 3736.65,1502 3758.62,1502 3769.62,1513 4279.35,1513 4366.35,1426 4652.35,1426 4668.35,1410 4934.79,1410 4942.79,1418 4978.75,1418 4983.75,1413 v1(4987,1413)
D7: J1.4 U2.63 U20.21 | length 3386
  Top Layer w8: U20.21@3300,1376 3303.25,1372.75 3303.25,1332.75 3349,1287 3385,1287 3407,1265 v1(3407.35,1265) ; v1(4988,1382) 4947,1423 4947,1590.64 5145.73,1789.37 U2.63@5220.47,1789.37
  Bottom Layer w8: J1.4@2637.8,960.63 2829.63,960.63 2885,1016 3158,1016 v1@3407,1265 ; v1(3407.35,1265) v1@3407,1265 ; v1(4988,1382) 4967,1403 4949,1403 4941,1395 4662.13,1395 4646.13,1411 4360.13,1411 4273.13,1498 3775.83,1498 3764.83,1487 3742.87,1487 3732.87,1477 3619,1477 v1@3407,1265
D8: J1.17 U2.11 | length 2107.4
  Top Layer w8: v1(2572,1097.43) 2608.04,1097.43 2645.96,1135.35 3021.01,1135.35 3229.37,927 4220.75,927 4229.75,918 v1(4233,918) ; v1(4322,1046) 4324.3,1048.3 4335.51,1048.3 4350.46,1063.25 4350.46,1086.29 U2.11@4354.17,1090
  Bottom Layer w8: J1.17@2480.31,1098.43 2571.01,1098.43 v1(2572,1097.43) ; v1(4233,918) 4233,990.79 4288.21,1046 v1(4322,1046)
D9: J1.15 U2.10 | length 2211.8
  Top Layer w8: v1(2547.24,1075.15) 2608.39,1075.15 2653.59,1120.35 3014.8,1120.35 3223.15,912 4194.75,912 4205.75,901 v1(4209,901) ; U2.10@4328.74,1102.36 v1@4328.74,1162.74
  Bottom Layer w8: J1.15@2480.31,1078.74 2540.41,1078.74 2544,1075.15 v1(2547.24,1075.15) ; v1(4209,901) 4209,988 4329,1108 v1(4329,1163)
D10: J1.13 U2.9 | length 2213.7
  Top Layer w8: v1(2572,1052.87) 2608.73,1052.87 2661.22,1105.35 3008.59,1105.35 3216.94,897 4171.77,897 4185.77,883 v1(4188.88,883) ; v1(4302,1163) 4302.57,1162.43 4302.57,1102.94 U2.9@4303.15,1102.36
  Bottom Layer w8: J1.13@2480.34,1059.03 2533.67,1059.03 2538.55,1054.15 2570.72,1054.15 v1(2572,1052.87) ; v1(4188.88,883) 4188,883.87 4188,988.21 4302,1102.21 v1(4302,1163)
D11: J1.11 U2.8 | length 2204
  Top Layer w8: v1(2547.24,1030.58) 2609.07,1030.58 2668.84,1090.35 3002.37,1090.35 3210.73,882 4150.18,882 4161.72,870.46 v1(4164.97,870.46) ; v1(4275,1163) 4276.28,1161.72 4276.28,1103.64 U2.8@4277.56,1102.36
  Bottom Layer w8: J1.11@2480.31,1039.37 2535.21,1039.37 2544,1030.58 v1(2547.24,1030.58) ; v1(4164.97,870.46) 4164.97,986.39 4275,1096.43 v1(4275,1163)
D12: J1.9 U2.6 | length 2177.4
  Top Layer w8: v1(2572,1008.3) 2609.42,1008.3 2675.47,1074.35 2997.16,1074.35 3204.51,867 4128.73,867 4137.73,858 v1(4140.97,858) ; v1(4226,1160) 4226.19,1159.81 4226.19,1102.55 U2.6@4226.38,1102.36
  Bottom Layer w8: J1.9@2480.31,1019.69 2528.44,1019.69 2538.55,1009.58 2570.72,1009.58 v1(2572,1008.3) ; v1(4140.97,858) 4140.97,858.57 4142,859.6 4142,984.64 4226,1068.64 v1(4226,1160)
D13: J1.7 U2.5 | length 2169.6
  Top Layer w8: v1(2547.24,986.02) 2609.76,986.02 2682.1,1058.35 2991.95,1058.35 3198.3,852 4105.91,852 4114.91,843 v1(4118.15,843) ; v1(4199.02,1158.96) 4199.9,1158.08 4199.9,1103.25 U2.5@4200.79,1102.36
  Bottom Layer w8: J1.7@2480.31,1000 2481.24,999.08 2527.84,999.08 2532.33,994.58 2535.43,994.58 2544,986.02 v1(2547.24,986.02) ; v1(4118.15,843) 4118.15,982.01 4199.02,1062.87 v1(4199.02,1158.96)
D14: J1.5 U2.4 | length 2165
  Top Layer w8: v1(2572,963.73) 2609.52,963.73 2688.14,1042.35 2986.73,1042.35 3192.09,837 4083.42,837 4092.42,828 v1(4095.66,828) ; v1(4172.02,1159) 4173.61,1157.41 4173.61,1103.95 U2.4@4175.2,1102.36
  Bottom Layer w8: J1.5@2480.31,980.31 2481.24,979.39 2524.17,979.39 2539.83,963.73 v1(2572,963.73) ; v1(4095.66,828) 4094.67,828.99 4094.67,979.74 4172.02,1057.09 v1(4172.02,1159)
D15: J1.3 U2.3 | length 2156
  Top Layer w8: v1(2547.24,941.45) 2608.45,941.45 2694.35,1027.35 2980.52,1027.35 3185.87,822 4060.32,822 4069.32,813 v1(4071.01,813) ; v1(4145.04,1157.88) 4147.32,1155.6 4147.32,1104.64 U2.3@4149.61,1102.36
  Bottom Layer w8: J1.3@2480.31,960.63 2481.24,959.71 2521.4,959.71 2533.93,947.18 2538.27,947.18 2544,941.45 v1(2547.24,941.45) ; v1(4071.01,813) 4071.01,977.29 4145.04,1051.32 v1(4145.04,1157.88)
EROM#: U2.2 U20.22 U20.24 | length 1176.1
  Top Layer w8: U20.22@3350,1376 3350,1345.19 3378.19,1317 3442.06,1317 3446.75,1321.69 ; U20.24@3450,1376 3446.75,1372.75 3446.75,1321.69 ; U2.2@4124.02,1102.36 4120.14,1106.24 4120.14,1150.86 4109,1162 4065,1162 4043,1140 4043,1076 4029,1062 3804,1062 3791,1075 3791,1170 3687,1274 3479,1274 3446.75,1306.25 3446.75,1321.69
GND: C1.2 C2.2 C3.2 C4.2 C5.2 C6.2 C7.2 C8.2 C9.2 C10.2 C11.2 C12.2 C13.2 C14.2 C15.2 C16.2 C17.2 C18.2 C19.2 C20.2 C21.2 C22.2 C23.2 C24.2 C25.2 C26.2 C28.2 C29.2 C30.2 C31.2 J1.1 J1.2 J1.60 J1.71 J1.72 J1.73 J1.74 M1.1 M2.1 M3.1 M4.1 R14.1 R16.1 R18.1 R20.1 R32.1 R33.1 R34.1 R35.1 U2.7 U2.12 U2.18 U2.19 U2.20 U2.21 U2.40 U2.53 U2.61 U2.64 U2.70 U2.80 U2.90 U2.91 U2.101 U2.120 U2.128 U2.137 U2.144 U2.156 U2.160 U7.21 U7.27 U7.35 U7.40 U20.16 | length 632.6
  Top Layer w8: 3171,1514 3193.96,1514 3194.96,1515 3298,1515 ; 3173,1566 3303,1566
  Top Layer w10: U2.101@4584.65,2348.43 4584.65,2298.35 4590,2293 ; v1@5156.19,1738.19 U2.61@5220.47,1738.19
  Top Layer w15: U7.35@3050,2359.45 3050,2331 3075,2306 ; U2.7@4251.97,1102.36 4251.59,1102.74 4251.59,1151.76 4250.5,1152.85 4250.5,1192.5 4252,1194
  Bottom Layer w8: J1.72@2637.8,1629.92 2638.72,1630.84 2682.04,1630.84 2692.2,1641 2694,1641
  Bottom Layer w20: v1(4630,1881) C11.2@4665.75,1880.98
  other v1: 3093,825 4185,825 4264,826 2784,835 4431,835 4986,836 4600.5,836.86 4725,837 5195,837 5095,838 2656,842 5289,843 2512,845 3064,858 4244,868 2442,891 2680,897 2594,899 2791,905 4521.06,907.63 5304,933 4281,939 3289,961 3770,964 3678,965 3502,968 4549,984 5248,984 5103,985 4956,996 3208,1000 4743,1010 4661,1029 5306,1060 4007,1137 3833,1153 5153,1158 3052,1162 4574,1176 3007,1180 5195,1180 2870,1200 4517,1202 3776.15,1240.28 4678.89,1253 4223,1263 3779,1268 5327,1272 4203,1298 3861,1304 3490,1305 3832,1305 3526,1307 4055,1315 5071,1385 5088,1413 5328,1433 5156,1485 5331,1512 3397,1515 5158,1517 2746,1529 4870,1536 3430,1558 3479,1586 5329,1594 5067,1604 4801,1608 2988,1643 2737,1654 4797,1663 4499,1684 5143,1684 4720,1685 4909,1690 2821,1719 2903,1721 3061,1722 4484,1726 5156,1738 5330,1754 5066,1758 2444,1789 5150,1814 2963,1874 2882,1880 3112,1888 2504,1892 2690,1896 5331,1914 2444,1921 2717,1940 2630,1970 5071,1970 5134,1978 4762,1995 2492,1999 4532,2025 5332,2074 2453,2079 3128,2081 4603,2096 3008.63,2107.57 4525,2114 4917,2122 4077,2143 4103,2169 5082,2171 2499,2189 5140,2263 4708,2271 4829,2275 4945,2278 5065,2278 4385,2280 2446,2285 2888,2291 3085,2295 3118,2295 2819,2296 2727,2300 5314,2352 3784,2386 4045,2389 3819,2392 2561,2395 3524,2413 2480,2433 5283,2447 3600,2448 3473,2457 2642,2461 2788,2510 2520,2533 5263,2552 5026,2554 2707,2555 5157,2584 4638,2600
HSYNC: R21.1 U2.69 | length 540
  Top Layer w10: v1(4755,1853) 4801,1899 5056,1899 5099.91,1942.91 U2.69@5220.47,1942.91
  Bottom Layer w10: R21.1@4729.9,1880 4729.9,1878.5 v1@4755.2,1853.2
